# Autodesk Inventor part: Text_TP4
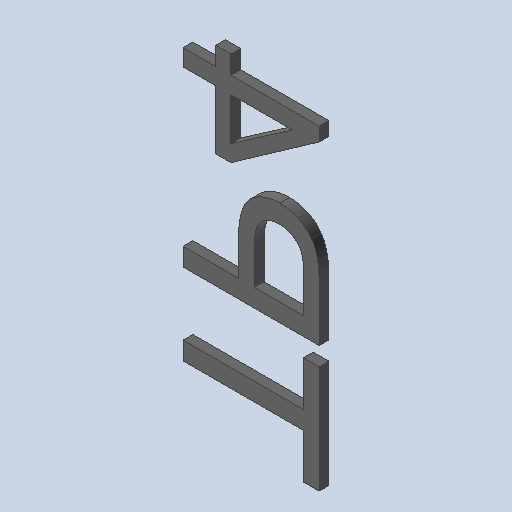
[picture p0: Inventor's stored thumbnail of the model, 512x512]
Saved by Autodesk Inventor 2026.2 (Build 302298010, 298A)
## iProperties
Created: 2026-10
Part Number: Text_TP4
Material: Générique
Document SubType Name: Modeling
Designer: mel
Density: 1 g/cm^3
Appearance: Par défaut
Author: mel
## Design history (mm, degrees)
feature "Base1"
feature "Base2"
feature "Base3"
node "Solide1"
node "Solide2"
node "Solide3"
